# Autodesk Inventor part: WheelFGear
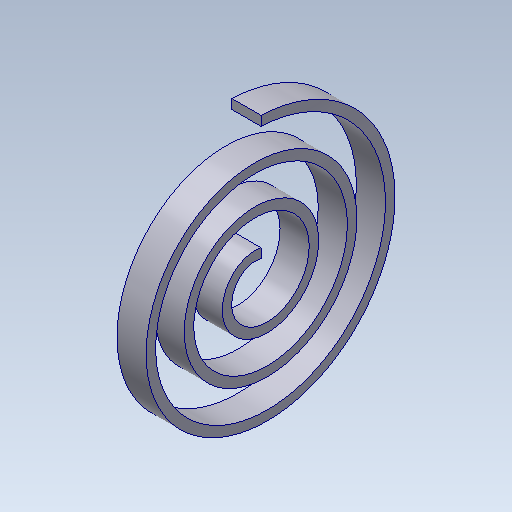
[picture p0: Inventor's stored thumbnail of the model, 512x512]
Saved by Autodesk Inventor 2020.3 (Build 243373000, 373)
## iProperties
Created: 2010-08
Part Number: WheelFGear
Document SubType Name: Modeling
Designer: nguyenducthang
Density: 1 g/cm^3
Mass: 31.2752 g
Surface Area: 209.173 cm^2
Volume: 31.2752 cm^3
Material: Generico
Appearance: Bianco freddo
Author: nguyenducthang
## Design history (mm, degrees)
sketch "Sketch69"
  geometry: L1 (0, 0)-(0, 75); L2 (0, 75)-(5, 75); L3 (5, 75)-(5, 40); L4 (5, 40)-(10, 40); L5 (10, 40)-(10, 0); L6 (72, 0)-(0, 0)
  constraints: 12 end point, 4 parallel, 1 perpendicular, 1 point on line, 1 vertical, 1 other
  dimensions: "d454" = 75 distance of L1.start L1.end; "d458" = 5 distance of L1.end L2.end; "d459" = 5 distance of L3.end L4.end; "d559" = 40 distance between parallel lines of L4 L6
revolve "Revolution7" sketch "Sketch69" stored, may be unused: angle "d462" = 90 deg
sketch "Sketch78"
  geometry: L1 (0, 75)-(5, 75) reference; L2 (0, -75)-(0, 75) reference; L3 (0, 8)-(-12.2, 8); L4 (0, 12)-(0, 8); L5 (0, 0)-(-29.088, 0); L6 (-12.2, 8)-(-12.2, 12); L7 (-12.2, 12)-(0, 12)
  constraints: 10 end point, 2 perpendicular, 1 collinear, 1 midpoint, 1 point on line
  dimensions: "d556" = 8 distance between parallel lines of L3 L5; "d557" = 4 distance of L3.end L6.end; "d558" = 12.2 distance of L6.end L4.start
coil "Coil9" sketch "Sketch78" pitch "d536" = 16; turns "d538" = 3; dims "d537" = 10, "d539" = 0, angle "d540" = 90 deg, angle "d541" = 90 deg, "d542" = 0, "d543" = 0
sketch "Sketch81"
  geometry: C1 r 75 at (0, 0) reference; C2 r 7.5 at (0, 0)
  constraints: 1 centre point, 1 coincident
  dimensions: "d560" = 15 diameter of C2
extrude "Extrusion65" cut sketch "Sketch81" extent not by distance; stored distance "d561" = 10; taper "d562" = 0 deg
sketch "Sketch82"
  geometry: C1 r 7.5 at (0, 0) reference; C2 r 75 at (0, 0) reference
extrude "Extrusion66" cut sketch "Sketch82" extent not by distance; stored distance "d563" = 10; taper "d564" = 0 deg
node "Solido1"
node "Corpi solidi"
node "Corpi di superficie"
other parameters: "d489" = 6.19982 (derived)
